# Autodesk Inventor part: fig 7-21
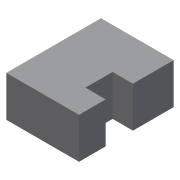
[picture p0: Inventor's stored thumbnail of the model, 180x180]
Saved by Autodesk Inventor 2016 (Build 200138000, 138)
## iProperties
Created: 2010-03
Part Number: fig 7-21
Document SubType Name: Modeling
Designer: CADSoft
Density: 1 g/cm^3
Material: Generic
Appearance: Default
Author: CADSoft
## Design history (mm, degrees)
sketch "Sketch1"
  geometry: L1 (-16.027, 20.205)-(19.726, 20.205); L2 (19.726, 20.205)-(19.726, -26.37); L3 (19.726, -26.37)-(-16.027, -26.37); L4 (-16.027, -26.37)-(-16.027, 20.205); 1 further point
  constraints: 8 end point, 2 parallel, 1 horizontal, 1 perpendicular
extrude "Extrusion1" new body sketch "Sketch1" distance "d0" = 20; taper "d1" = 0 deg
sketch "Sketch2"
  geometry: L1 (-20, 46.575)-(-20, 0) reference; L2 (0, 46.575)-(0, 0) reference; L3 (-20, 13.159)-(0, 13.159); L4 (0, 13.159)-(0, 33.527); L5 (0, 33.527)-(-20, 33.527); L6 (-20, 33.527)-(-20, 13.159); 1 further point
  constraints: 8 end point, 2 parallel, 2 point on line, 1 horizontal, 1 perpendicular
extrude "Extrusion2" cut sketch "Sketch2" distance "d2" = 10; taper "d3" = 0 deg
node "Direct Edit2"
body "Solid1"
move_body "Move2" dims "d9" = 7
other parameters: "d7" = 0, "d8" = 0
